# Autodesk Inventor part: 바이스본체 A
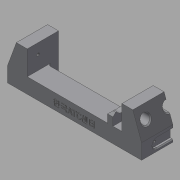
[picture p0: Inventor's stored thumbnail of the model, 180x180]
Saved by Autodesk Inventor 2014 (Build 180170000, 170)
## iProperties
Created: 2017-04
Part Number: 바이스본체 A
Material: 일반
Document SubType Name: Modeling
Designer: mduedu
Density: 1 g/cm^3
Appearance: 기본값
Author: mduedu
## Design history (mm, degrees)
sketch "스케치1"
  geometry: L1 (-75, 0)-(75, 0); L2 (-75, 0)-(-75, 17); L3 (-53, 17)-(53, 17); L4 (75, 17)-(75, 0); L5 (-75, 17)-(-65.173, 44); L6 (-65.173, 44)-(-53, 44); L7 (-53, 44)-(-53, 17); L8 (0, 0)-(0, 17); L9 (75, 17)-(65.173, 44); L10 (65.173, 44)-(53, 44); L11 (53, 44)-(53, 17); 1 further point
  constraints: 22 end point, 4 perpendicular, 2 horizontal alignment, 2 midpoint, 2 symmetric about line, 1 coincident, 1 collinear, 1 horizontal, 1 vertical
  dimensions: "d0" = 150 distance of L1.start L1.end; "d1" = 17 distance of L1.start L2.end; "d2" = 27 distance of L3.start L6.end; "d3" = 22 distance of L3.start L2.end; "d4" = 70 deg angle of L3 L5; "d54" = 20 deg angle of L9 L4
extrude "돌출1" new body sketch "스케치1" stored distance "d5" = 70; taper "d6" = 0 deg
sketch "스케치2"
  geometry: L1 (0, 70)-(106, 70) reference; L2 (106, 70)-(106, 0) reference; L3 (106, 0)-(0, 0) reference; L4 (0, 47)-(106, 47); L5 (106, 47)-(106, 23); L6 (106, 23)-(0, 23); L7 (0, 23)-(0, 47); L8 (0, 70)-(0, 0) reference; 2 further points
  constraints: 8 end point, 2 parallel, 2 point on line, 1 horizontal, 1 horizontal alignment, 1 midpoint, 1 perpendicular
  dimensions: "d7" = 24 distance between parallel lines of L6 L4
extrude "돌출2" cut sketch "스케치2" stored distance "d9" = 70; taper "d10" = 0 deg
sketch "스케치3"
  geometry: L1 (22, -23)-(128, -23) reference; L2 (128, -47)-(22, -47) reference; L3 (22, -18)-(128, -18); L4 (128, -52)-(22, -52); L5 (22, -18)-(22, -52); L6 (128, -18)-(128, -52); 1 further point
  constraints: 8 end point, 3 parallel, 2 point on line, 1 perpendicular
  dimensions: "d11" = 5 distance between parallel lines of L3 L1; "d12" = 5 distance between parallel lines of L4 L2
extrude "돌출3" cut sketch "스케치3" distance "d13" = 12; taper "d14" = 0 deg
fillet "모깎기1" dims "d15" = 3, "d16" = 3
sketch "스케치4"
  geometry: L1 (103, 23)-(3, 23) reference; L2 (0, 26)-(0, 0) reference; L3 (106, 0)-(0, 0) reference; L4 (106, 26)-(106, 0) reference; L5 (96, 0)-(90, 0); L6 (90, 0)-(90, 19.5); L7 (96, 19.5)-(96, 0); L8 (90, 19.5)-(96, 19.5); A1 r 3 centre (3, 26) between (0, 26) and (3, 23) reference; A2 r 3 centre (103, 26) between (103, 23) and (106, 26) reference; 1 further point
  constraints: 8 end point, 2 perpendicular, 1 horizontal, 1 parallel, 1 point on line
  dimensions: "d17" = 10 distance between parallel lines of L7 L4; "d18" = 6 distance between parallel lines of L7 L6; "d27" = 3.5 distance between parallel lines of L8 L1
extrude "돌출4" join sketch "스케치4" distance "d19" = 12; taper "d20" = 0 deg
chamfer "모따기1" distance "d21" = 3; stored, may be unused: second distance "d22" = 2, angle "d23" = 45 deg
chamfer "모따기2" distance "d24" = 3; stored, may be unused: second distance "d25" = 2, angle "d26" = 45 deg
sketch "스케치5"
  geometry: L1 (-15.5, 35.8)-(-15.5, -25.8) reference; L2 (19.5, 0)-(0, 0) reference; C1 r 6.5 at (9.5, 15); 1 further point
  constraints: 1 centre point
  dimensions: "d28" = 13 diameter of C1; "d30" = 15 distance from line of C1.centre L2; "d31" = 25 distance from line of C1.centre L1
extrude "돌출5" cut sketch "스케치5" stored distance "d32" = 12; taper "d33" = 0 deg
sketch "스케치6"
  geometry: C1 r 5 at (-10, 15); C2 r 5 at (-60, 15); A1 r 6.5 centre (-10, 15) between (-15.766, 12) and (-4.234, 12) reference; A2 r 6.5 centre (-60, 15) between (-65.766, 12) and (-54.234, 12) reference; 1 further point
  constraints: 2 centre point, 2 coincident
  dimensions: "d34" = 10 diameter of C1; "d35" = 10 diameter of C2 (= d34)
extrude "돌출6" cut sketch "스케치6" stored distance "d36" = 12; taper "d37" = 0 deg
chamfer "모따기3" distance "d38" = 1; stored, may be unused: second distance "d39" = 2, angle "d40" = 45 deg
chamfer "모따기4" distance "d41" = 1; stored, may be unused: second distance "d42" = 2, angle "d43" = 45 deg
sketch "스케치7"
  geometry: L1 (-35, 35.8)-(-35, -25.8) reference; L2 (-70, 0)-(0, 0) reference; C1 r 5 at (-35, 15); 1 further point
  constraints: 1 centre point, 1 point on line
  dimensions: "d44" = 10 diameter of C1; "d45" = 15 distance from line of C1.centre L2
extrude "돌출7" cut sketch "스케치7" stored distance "d46" = 12; taper "d47" = 0 deg
chamfer "모따기5" distance "d48" = 1; stored, may be unused: second distance "d49" = 2, angle "d50" = 45 deg
node "작업축1"
sketch "스케치8"
  geometry: L1 (-105, 32)-(105, 32) reference; L2 (58, 32)-(64, 32); L3 (64, 32)-(64, 40); L4 (64, 40)-(58, 40); L5 (58, 40)-(58, 32); L6 (53, 38)-(53, 26) reference; 1 further point
  constraints: 8 end point, 2 parallel, 1 horizontal, 1 perpendicular, 1 point on line
  dimensions: "d51" = 5 distance from line of L6 L2.start; "d52" = 6 distance of L3.end L4.end; "d53" = 16 diameter of L4 L1
revolve "회전1" sketch "스케치8" stored, may be unused: angle "d55" = 90 deg
fillet "모깎기2"
chamfer "모따기6" distance "d56" = 1; stored, may be unused: second distance "d57" = 2, angle "d58" = 45 deg
sketch "스케치9"
  geometry: L1 (17.5, 3)-(52.5, 3); L2 (52.5, 13)-(17.5, 13); L3 (70, 0)-(0, 0) reference; L4 (17.5, 8)-(52.5, 8); A1 r 5 centre (17.5, 8) between (17.5, 13) and (17.5, 3); A2 r 5 centre (52.5, 8) between (52.5, 3) and (52.5, 13); 3 further points
  constraints: 6 end point, 4 point on circle, 3 tangent, 2 centre point, 2 midpoint, 2 parallel, 1 horizontal, 1 vertical alignment
  dimensions: "d59" = 35 distance of L4.start L4.end; "d61" = 5 radius of A2; "d62" = 8 distance between parallel lines of L3 L4
extrude "돌출8" cut sketch "스케치9" distance "d63" = 3; taper "d64" = 0 deg
chamfer "모따기7" distance "d65" = 1; stored, may be unused: second distance "d66" = 2, angle "d67" = 45 deg
chamfer "모따기8" distance "d68" = 1; stored, may be unused: second distance "d69" = 2, angle "d70" = 45 deg
feature "분할1"
sketch "스케치10"
  geometry: L1 (35, 27)-(0, 27) reference; L2 (0, 0)-(0, 27) reference; 1 further point
  dimensions: "d85" = 11.5 distance from line of point (12, 15.5) L1; "d86" = 12 distance from line of point (12, 15.5) L2
hole "구멍1" sketch "스케치10" at (12, 15.5) diameter "d71" = 3.242; stored, may be unused: countersink angle "d75" = 90 deg, drill point angle "d77" = 120 deg; dims "d72" = 6, "d73" = 4, "d74" = 2, "d76" = 8
sketch "스케치11"
  geometry: A1 r 5 centre (17.5, 8) between (17.5, 13) and (17.5, 3) reference; 1 further point
  constraints: 1 coincident
hole "구멍3" sketch "스케치11" at (17.5, 8) diameter "d78" = 2.459; stored, may be unused: countersink angle "d82" = 90 deg, drill point angle "d84" = 120 deg; dims "d79" = 4.5, "d80" = 4, "d81" = 2, "d83" = 6
sketch "스케치12"
  geometry: L1 (-75, 0)-(75, 0) reference; 3 further points
  constraints: 1 midpoint, 1 vertical alignment, 1 other
  dimensions: "d87" = 8 distance of point (0, 8) point (0, 0)
feature "엠보싱1" sketch "스케치12" dims "d7" = 24, "d88" = 0.5, "d89" = 0
node "솔리드1"
mirror "대칭1"
mirror "대칭2"
mirror "대칭3"
mirror "대칭4"
node "투영된 루프1"
